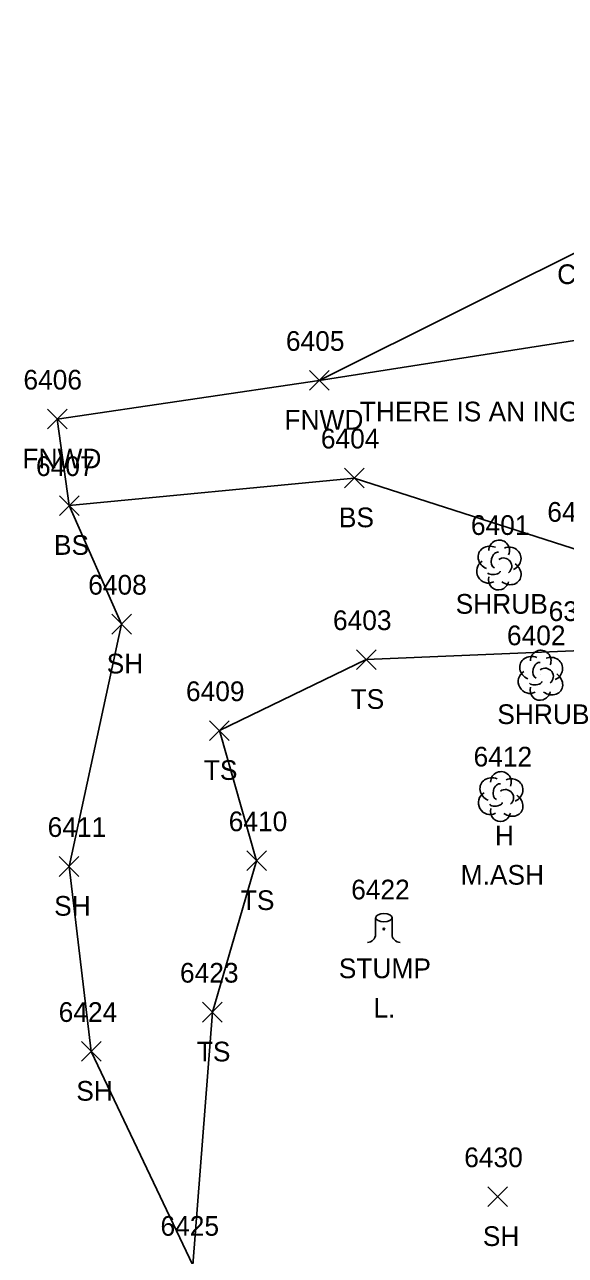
# Model space of a CAD drawing. Extents: x 1472233 to 1475777, y 540726 to 543442.
# Drawn here: x 1472233.4 to 1472288.4, y 541668.7 to 541793.6 of the extents above; entities that cross this region are included whole.
import ezdxf

# ---------------------------------------------------------------- set-up
doc = ezdxf.new("R2010")
doc.units = 0
for name, color, linetype in [('L_A', 7, 'Continuous'), ('L_C', 7, 'Continuous'), ('L_I', 7, 'Continuous'), ('L_TIC', 7, 'Continuous'), ('LELB', 7, 'Continuous'), ('LFNC', 7, 'Continuous'), ('LSH', 7, 'Continuous'), ('LSOGP', 7, 'Continuous'), ('LTD', 7, 'Continuous'), ('LTS', 7, 'Continuous')]:
    doc.layers.add(name, color=color, linetype=linetype)

msp = doc.modelspace()

# ---------------------------------------------------------------- linework, layer by layer
at = {"layer": 'L_TIC'}
for points in [[(1472262.36, 541756.5), (1472264.36, 541758.5)], [(1472264.36, 541756.5), (1472262.36, 541758.5)], [(1472235.75, 541752.57), (1472237.75, 541754.57)], [(1472237.75, 541752.57), (1472235.75, 541754.57)], [(1472265.91, 541746.59), (1472267.91, 541748.59)], [(1472267.91, 541746.59), (1472265.91, 541748.59)], [(1472236.97, 541743.79), (1472238.97, 541745.79)], [(1472238.97, 541743.79), (1472236.97, 541745.79)], [(1472242.28, 541731.75), (1472244.28, 541733.75)], [(1472244.28, 541731.75), (1472242.28, 541733.75)], [(1472267.13, 541728.15), (1472269.13, 541730.15)], [(1472269.13, 541728.15), (1472267.13, 541730.15)], [(1472252.22, 541720.94), (1472254.22, 541722.94)], [(1472254.22, 541720.94), (1472252.22, 541722.94)], [(1472236.95, 541707.15), (1472238.95, 541709.15)], [(1472238.95, 541707.15), (1472236.95, 541709.15)], [(1472255.99, 541707.73), (1472257.99, 541709.73)], [(1472257.99, 541707.73), (1472255.99, 541709.73)], [(1472251.51, 541692.36), (1472253.51, 541694.36)], [(1472253.51, 541692.36), (1472251.51, 541694.36)], [(1472239.2, 541688.37), (1472241.2, 541690.37)], [(1472241.2, 541688.37), (1472239.2, 541690.37)], [(1472280.48, 541673.62), (1472282.48, 541675.62)], [(1472282.48, 541673.62), (1472280.48, 541675.62)]]:
    msp.add_lwpolyline(points, dxfattribs=at)
at = {"layer": 'LELB'}
for points in [[(1472299.33, 541724.33), (1472289.99, 541740.15), (1472266.91, 541747.59), (1472237.97, 541744.79)], [(1472299.33, 541724.33), (1472289.98, 541730.07), (1472268.13, 541729.15), (1472253.22, 541721.94), (1472256.99, 541708.73), (1472252.51, 541693.36), (1472250.53, 541667.66), (1472279.15, 541637.99), (1472299.42, 541598.15), (1472323.99, 541557.12), (1472324.06, 541530.56)]]:
    msp.add_lwpolyline(points, dxfattribs=at)
at = {"layer": 'LFNC'}
msp.add_lwpolyline([(1472292.99, 541772.28), (1472294.25, 541762.34), (1472263.36, 541757.5), (1472236.75, 541753.57)], dxfattribs=at)
at = {"layer": 'LSH'}
for p, q in [((1472281.58, 541738.81), (1472281.58, 541738.81)), ((1472281.58, 541738.81), (1472281.58, 541738.81)), ((1472285.81, 541727.61), (1472285.81, 541727.61)), ((1472285.81, 541727.61), (1472285.81, 541727.61))]:
    msp.add_line(p, q, dxfattribs=at)
for centre in [(1472281.63, 541740.24), (1472285.85, 541729.05)]:
    msp.add_arc(centre, 1.05, 335.5272, 180.9563, dxfattribs=at)
for centre, major_axis, ratio, start_param, end_param in [((1472280.79, 541739.47), (1.21, -0.51), 0.895232, 1.570796, 4.712389), ((1472282.62, 541739.39), (-1.14, -0.48), 0.949671, 1.570796, 4.712389), ((1472280.5, 541738.1), (0.58, -1.04), 0.959034, 3.141593, 6.283185), ((1472281.37, 541739.26), (-0.208, -0.792), 0.645439, 3.141593, 6.283185), ((1472282.08, 541738.64), (-0.5, 0.667), 0.989748, 3.141593, 6.283185), ((1472281.12, 541738.06), (-0.625, -0.083), 0.423636, 0, 3.141593), ((1472282.58, 541737.97), (-1.09, 0.79), 0.841452, 1.570796, 4.712389), ((1472281.58, 541737.31), (0.26, 1.06), 0.942809, 1.570796, 4.712389), ((1472285.01, 541728.28), (1.21, -0.51), 0.895232, 1.570796, 4.712389), ((1472286.85, 541728.2), (-1.14, -0.48), 0.949671, 1.570796, 4.712389), ((1472284.72, 541726.9), (0.58, -1.04), 0.959034, 3.141593, 6.283185), ((1472285.6, 541728.07), (-0.208, -0.792), 0.645439, 3.141593, 6.283185), ((1472286.31, 541727.45), (-0.5, 0.667), 0.989748, 3.141593, 6.283185), ((1472285.35, 541726.86), (-0.625, -0.083), 0.423636, 0, 3.141593), ((1472286.81, 541726.78), (-1.09, 0.79), 0.841452, 1.570796, 4.712389), ((1472285.81, 541726.11), (0.26, 1.06), 0.942809, 1.570796, 4.712389)]:
    msp.add_ellipse(centre, major_axis=major_axis, ratio=ratio, start_param=start_param, end_param=end_param, dxfattribs=at)
at = {"layer": 'LSOGP'}
msp.add_lwpolyline([(1472250.53, 541667.66), (1472240.2, 541689.37), (1472237.95, 541708.15), (1472243.28, 541732.75), (1472237.97, 541744.79), (1472236.75, 541753.57), (1472263.36, 541757.5), (1472292.99, 541772.28), (1472293.87, 541772.28), (1472311.61, 541774.94), (1472311.71, 541774.99), (1472312.69, 541775.1), (1472313.86, 541775.32), (1472313.53, 541780.33), (1472308.58, 541803.57)], dxfattribs=at)
at = {"layer": 'LTD'}
msp.add_line((1472281.77, 541715.3), (1472281.77, 541715.3), dxfattribs=at)
msp.add_line((1472281.77, 541715.3), (1472281.77, 541715.3), dxfattribs=at)
msp.add_arc((1472281.81, 541716.73), 1.05, 335.5272, 180.9563, dxfattribs=at)
for centre, major_axis, ratio, start_param, end_param in [((1472280.97, 541715.96), (1.21, -0.51), 0.895232, 1.570796, 4.712389), ((1472281.56, 541715.75), (-0.208, -0.792), 0.645439, 3.141593, 6.283185), ((1472282.81, 541715.88), (-1.14, -0.48), 0.949671, 1.570796, 4.712389), ((1472280.68, 541714.59), (0.58, -1.04), 0.959034, 3.141593, 6.283185), ((1472282.27, 541715.13), (-0.5, 0.667), 0.989748, 3.141593, 6.283185), ((1472282.77, 541714.46), (-1.09, 0.79), 0.841452, 1.570796, 4.712389), ((1472281.31, 541714.55), (-0.625, -0.083), 0.423636, 0, 3.141593), ((1472281.77, 541713.8), (0.26, 1.06), 0.942809, 1.570796, 4.712389)]:
    msp.add_ellipse(centre, major_axis=major_axis, ratio=ratio, start_param=start_param, end_param=end_param, dxfattribs=at)
at = {"layer": 'LTS'}
for p, q in [((1472269.08, 541702.95), (1472269.08, 541701.28)), ((1472270.75, 541702.78), (1472270.75, 541702.95)), ((1472270.75, 541702.95), (1472270.75, 541701.28)), ((1472269.92, 541701.8), (1472269.92, 541701.8)), ((1472269.92, 541701.8), (1472269.92, 541701.8)), ((1472269.92, 541701.78), (1472269.92, 541701.78))]:
    msp.add_line(p, q, dxfattribs=at)
msp.add_circle((1472269.92, 541701.8), 0.0833, dxfattribs=at)
for centre, start, end in [((1472268.25, 541701.28), 270, 360), ((1472271.58, 541701.28), 180, 270)]:
    msp.add_arc(centre, 0.833, start, end, dxfattribs=at)
msp.add_ellipse((1472269.92, 541702.95), major_axis=(-0.833, 0), ratio=0.5, dxfattribs=at)

# ---------------------------------------------------------------- texts
at = {"layer": 'L_A'}
for s, p in [('CONCPAD', (1472287.52, 541767.28)), ('FNWD', (1472259.82, 541752.5)), ('FNWD', (1472233.21, 541748.57)), ('BS', (1472265.35, 541742.59)), ('BS', (1472236.41, 541739.79)), ('SHRUB', (1472277.21, 541733.81)), ('SH', (1472241.77, 541727.75)), ('TS', (1472266.54, 541724.15)), ('SHRUB', (1472281.44, 541722.61)), ('TS', (1472251.63, 541716.94)), ('H', (1472281.2, 541710.3)), ('TS', (1472255.39, 541703.73)), ('SH', (1472236.43, 541703.15)), ('STUMP', (1472265.34, 541696.81)), ('TS', (1472250.92, 541688.36)), ('SH', (1472238.68, 541684.37)), ('SH', (1472279.97, 541669.62))]:
    msp.add_text(s, height=2, dxfattribs=at).set_placement(p)
at = {"layer": 'L_C'}
for s, p in [('THERE IS AN INGROUND POOL FNWD', (1472267.48, 541753.34)), ('M.ASH', (1472277.72, 541706.3)), ('L.', (1472268.86, 541692.81))]:
    msp.add_text(s, height=2, dxfattribs=at).set_placement(p)
at = {"layer": 'L_I'}
for s, p in [('6405', (1472259.97, 541760.5)), ('6406', (1472233.31, 541756.57)), ('6404', (1472263.52, 541750.59)), ('6407', (1472234.59, 541747.79)), ('6400', (1472286.52, 541743.15)), ('6401', (1472278.76, 541741.81)), ('6408', (1472239.89, 541735.75)), ('6403', (1472264.75, 541732.15)), ('6399', (1472286.66, 541733.07)), ('6402', (1472282.42, 541730.61)), ('6409', (1472249.82, 541724.94)), ('6412', (1472279.03, 541718.3)), ('6411', (1472235.77, 541711.15)), ('6410', (1472254.16, 541711.73)), ('6422', (1472266.6, 541704.81)), ('6423', (1472249.21, 541696.36)), ('6424', (1472236.89, 541692.37)), ('6430', (1472278.08, 541677.62)), ('6425', (1472247.23, 541670.66))]:
    msp.add_text(s, height=2, dxfattribs=at).set_placement(p)

doc.saveas('drawing.dxf')
